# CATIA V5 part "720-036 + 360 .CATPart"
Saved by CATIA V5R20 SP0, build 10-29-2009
Part number: 720-036 + 360 
Revision: QUALSIASI
Definition: SCONOSCIUTO
Nomenclature: 720-036 + 360 
Source: Unknown
Bounding box of the stored display mesh (mm): x -45 to 45, y -5 to 360, z -21 to 21
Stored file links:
  C:\Users\Utente\Desktop\IO LAVORO\3D X SITO CF\X 3D SITO CF 27-09-2020\720\720-036 + 360 .CATPart
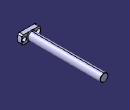
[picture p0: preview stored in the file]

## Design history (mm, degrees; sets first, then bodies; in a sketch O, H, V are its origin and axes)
Body1 "NONE" (main body)
  Solid1: solid without history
